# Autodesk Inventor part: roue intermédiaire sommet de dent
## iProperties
Shininess: 64.0
Length Units: 11269
Angle Units: 11279
Time Units: 11290
Mass Units: 11283
Length Display Precision: 3
Angle Display Precision: 2
Compacted: True
Part Number: roue intermédiaire sommet de dent
Document SubType Name: Modeling
Created: 2004-09
Material: Par défaut
Designer: Administrateur
Density: 1 g/cm^3
Density: 0.0
Volumn: 0.0
Area: 0.0
PropertySet Name: Model Information
Control State: 0
Master: False
Checked Out: False
Author: Administrateur
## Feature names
1. Extrusion1
